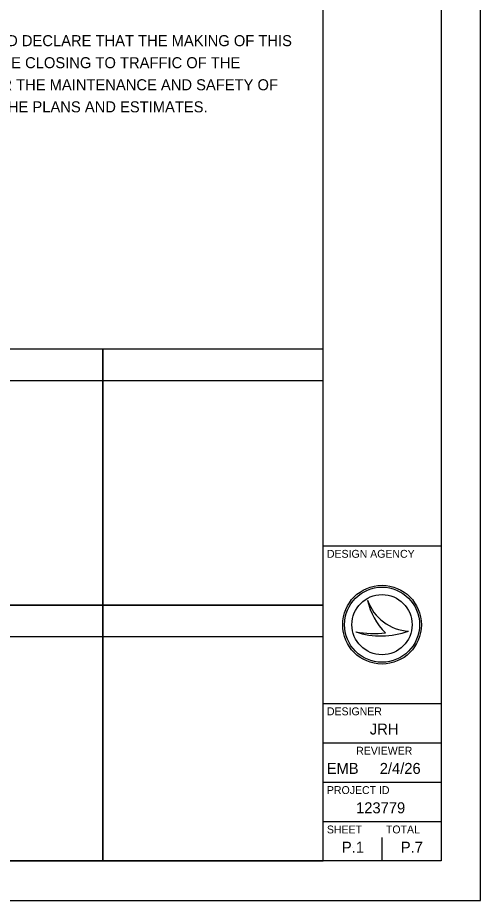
# Model space of a CAD drawing. Extents: x 0 to 34, y 0 to 22.
# Drawn here: x 28.12 to 34, y 0 to 11.21 of the extents above; entities that cross this region are included whole.
import ezdxf

# ---------------------------------------------------------------- set-up
doc = ezdxf.new("R2010")
doc.units = 0
for name, color, linetype in [('Default', 7, 'Continuous'), ('SH_Border', 7, 'Continuous'), ('SH_Cut_Line', 7, 'Continuous'), ('SH_Data', 7, 'Continuous')]:
    doc.layers.add(name, color=color, linetype=linetype)

msp = doc.modelspace()

# ---------------------------------------------------------------- linework, layer by layer
at = {"layer": 'SH_Border'}
for p, q in [((32, 0.5), (32, 21.5)), ((32, 4.5), (33.5, 4.5)), ((32, 2.5), (33.5, 2.5)), ((32, 2), (33.5, 2)), ((32, 1.5), (33.5, 1.5)), ((32, 1), (33.5, 1))]:
    msp.add_line(p, q, dxfattribs=at)
msp.add_lwpolyline([(1.5, 21.5), (33.5, 21.5), (33.5, 0.5), (1.5, 0.5)], close=True, dxfattribs=at)
at = {"layer": 'SH_Cut_Line'}
msp.add_lwpolyline([(0, 0), (34, 0), (34, 22), (0, 22)], close=True, dxfattribs=at)
at = {"layer": 'SH_Data'}
for p, q in [((26.4, 6.6), (29.2, 6.6)), ((29.2, 6.6), (32, 6.6)), ((32.567, 3.81), (32.567, 3.81)), ((32.75, 3.5), (32.75, 3.5)), ((32.417, 3.41), (32.417, 3.41)), ((33.087, 3.419), (33.087, 3.419)), ((26.4, 3.35), (29.2, 3.35)), ((29.2, 3.35), (32, 3.35)), ((32.75, 0.5), (32.75, 0.8)), ((32.375, 0.675), (32.375, 0.675))]:
    msp.add_line(p, q, dxfattribs=at)
for points in [[(29.2, 7), (26.4, 7), (26.4, 3.75), (29.2, 3.75)], [(32, 7), (29.2, 7), (29.2, 3.75), (32, 3.75)], [(29.2, 3.75), (26.4, 3.75), (26.4, 0.5), (29.2, 0.5)], [(32, 3.75), (29.2, 3.75), (29.2, 0.5), (32, 0.5)]]:
    msp.add_lwpolyline(points, close=True, dxfattribs=at)
for radius in [0.5, 0.477, 0.477, 0.382]:
    msp.add_circle((32.75, 3.5), radius, dxfattribs=at)
for centre, radius, start, end in [((33.116, 3.998), 0.58, 198.9257, 198.9319), ((33.347, 3.97), 0.796, 191.6379, 191.6421), ((33.116, 3.998), 0.58, 198.9319, 267.1657), ((33.347, 3.97), 0.796, 191.6421, 226.0947), ((32.739, 4.37), 1.013, 251.4576, 290.0832), ((32.648, 4.654), 1.266, 259.4964, 259.4995), ((32.739, 4.37), 1.013, 251.4527, 251.4576), ((32.648, 4.654), 1.266, 259.4995, 276.6672)]:
    msp.add_arc(centre, radius, start, end, dxfattribs=at)

# ---------------------------------------------------------------- texts
at = {"layer": 'Default'}
for s, p in [('I HEREBY APPROVE THESE PLANS AND DECLARE THAT THE MAKING OF THIS', (24.5, 10.846)), ('IMPROVEMENT WILL NOT REQUIRE THE CLOSING TO TRAFFIC OF THE', (24.5, 10.566)), ('HIGHWAY AND THAT PROVISIONS FOR THE MAINTENANCE AND SAFETY OF', (24.5, 10.286)), ('TRAFFIC WILL BE AS SET FORTH ON THE PLANS AND ESTIMATES.', (24.5, 10.006))]:
    msp.add_text(s, height=0.14, dxfattribs=at).set_placement(p)
at = {"layer": 'SH_Data'}
for s, height, p in [('DESIGN AGENCY', 0.1, (32.05, 4.35)), ('DESIGNER', 0.1, (32.05, 2.35)), ('JRH', 0.14, (32.595, 2.105)), ('REVIEWER', 0.1, (32.422, 1.85)), ('EMB', 0.14, (32.047, 1.605)), ('2/4/26', 0.14, (32.721, 1.605)), ('PROJECT ID', 0.1, (32.05, 1.35)), ('123779', 0.14, (32.42, 1.105)), ('SHEET', 0.1, (32.05, 0.85)), ('TOTAL', 0.1, (32.8, 0.85)), ('P.1', 0.14, (32.24, 0.605)), ('P.7', 0.14, (32.989, 0.605))]:
    msp.add_text(s, height=height, dxfattribs=at).set_placement(p)

doc.saveas('drawing.dxf')
